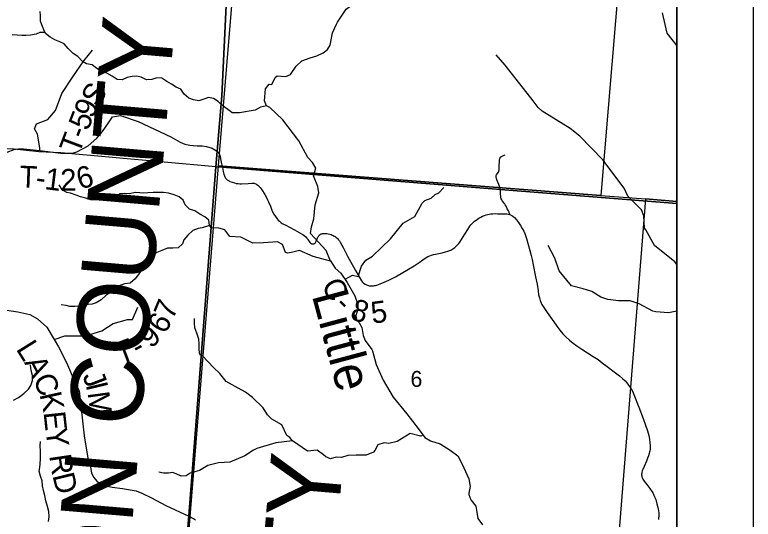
# Model space of a CAD drawing. Extents: x 0 to 42, y 0 to 22.
# Drawn here: x 8.033 to 9, y 16.545 to 17.205 of the extents above; entities that cross this region are included whole.
import ezdxf

# ---------------------------------------------------------------- set-up
doc = ezdxf.new("R2010")
doc.units = 0
for name, color, linetype in [('GM_X_County_Road', 7, 'Continuous'), ('GM_X_County_Road_Text', 7, 'Continuous'), ('GM_X_County_Text', 7, 'Continuous'), ('GM_X_Minor_River', 7, 'Continuous'), ('GM_X_Minor_River_Text', 7, 'Continuous'), ('GM_X_Section', 7, 'Continuous'), ('GM_X_Section_Text', 7, 'Continuous'), ('GM_X_Township', 7, 'Continuous'), ('GM_X_Township_Road', 7, 'Continuous'), ('GM_X_Township_Road_Text', 7, 'Continuous'), ('GM_X_Unincorporated', 7, 'Continuous'), ('SH_Cut_Line', 7, 'Continuous'), ('SH_Data', 7, 'Continuous')]:
    doc.layers.add(name, color=color, linetype=linetype)

msp = doc.modelspace()

# ---------------------------------------------------------------- linework, layer by layer
at = {"layer": 'GM_X_County_Road'}
for points in [[(8.29867, 17.02595), (8.29939, 17.02503), (8.30004, 17.02418), (8.3006, 17.02343), (8.30115, 17.02257), (8.30152, 17.0218), (8.30186, 17.02081), (8.30223, 17.01943), (8.30291, 17.01622), (8.3038, 17.012), (8.30509, 17.00589), (8.30528, 17.00492)], [(8.30528, 17.00492), (8.30629, 16.99983), (8.30713, 16.99616), (8.30787, 16.99385), (8.30833, 16.99284), (8.30888, 16.99182), (8.30938, 16.99108), (8.3103, 16.99), (8.31146, 16.98898), (8.31301, 16.98789), (8.31391, 16.98735), (8.31495, 16.98684), (8.31785, 16.98564), (8.32085, 16.98472), (8.3233, 16.98422), (8.32463, 16.98402), (8.32589, 16.9839), (8.32789, 16.98378), (8.33011, 16.98372), (8.33911, 16.98424), (8.34363, 16.98454), (8.34548, 16.98449), (8.34659, 16.98436), (8.34758, 16.98412), (8.34887, 16.98359), (8.34961, 16.98322), (8.35048, 16.98273), (8.35177, 16.98177), (8.3526, 16.9811), (8.35347, 16.98024), (8.35475, 16.97873), (8.356, 16.97713), (8.35698, 16.97571), (8.36067, 16.96976), (8.36286, 16.96582), (8.36438, 16.96273), (8.36566, 16.95998), (8.368, 16.95444), (8.36948, 16.95049), (8.37087, 16.94712), (8.37252, 16.944), (8.37457, 16.9408), (8.37695, 16.93772), (8.37839, 16.93612), (8.37975, 16.9348), (8.3811, 16.93365), (8.38233, 16.9327), (8.38361, 16.9318), (8.38525, 16.93086), (8.38825, 16.92938), (8.39293, 16.92708), (8.39959, 16.92363), (8.40884, 16.91828), (8.41034, 16.91741), (8.41219, 16.91611), (8.41436, 16.9141), (8.41582, 16.91255), (8.41649, 16.91174), (8.41709, 16.91087), (8.4179, 16.90964), (8.41931, 16.90758), (8.42002, 16.90664), (8.42074, 16.90597), (8.42124, 16.90565), (8.42192, 16.90532), (8.42249, 16.90511), (8.42333, 16.905), (8.42402, 16.90502), (8.42464, 16.90516), (8.42522, 16.90534), (8.42584, 16.9057), (8.42649, 16.9062), (8.42702, 16.90681), (8.42755, 16.90765), (8.42806, 16.90872), (8.42991, 16.91309), (8.43033, 16.91394), (8.43094, 16.91495), (8.43144, 16.91565), (8.43208, 16.91636), (8.43319, 16.91734), (8.43372, 16.91766), (8.43451, 16.91805), (8.43534, 16.91835), (8.43623, 16.91858), (8.43789, 16.91879), (8.43911, 16.91884), (8.44052, 16.91879), (8.44205, 16.91863), (8.44387, 16.91833), (8.44579, 16.91787), (8.4476, 16.91727), (8.44891, 16.91667), (8.45031, 16.91599), (8.45154, 16.9153), (8.45267, 16.9146), (8.45404, 16.91362), (8.45531, 16.91255), (8.45642, 16.91149), (8.45734, 16.91052), (8.45847, 16.9091), (8.4595, 16.9075), (8.46361, 16.89969), (8.46915, 16.88893), (8.4793, 16.87032), (8.48411, 16.86194), (8.48719, 16.85689), (8.48859, 16.85512), (8.49002, 16.85385), (8.49203, 16.85245), (8.49364, 16.85163), (8.49528, 16.85106), (8.4966, 16.85069), (8.49783, 16.8504), (8.49902, 16.85028), (8.50033, 16.85019), (8.50144, 16.85024), (8.50292, 16.8504), (8.50428, 16.85061), (8.50576, 16.85089), (8.50736, 16.8513), (8.51151, 16.8527), (8.51713, 16.85488), (8.52289, 16.85747), (8.53176, 16.86223), (8.5486, 16.87188), (8.55604, 16.87644), (8.56265, 16.88092), (8.56758, 16.88441), (8.57214, 16.88729), (8.57432, 16.88852), (8.57682, 16.88963), (8.57908, 16.89049), (8.58134, 16.89119), (8.58411, 16.89184), (8.5883, 16.89268), (8.59281, 16.89357), (8.59741, 16.8946), (8.60044, 16.89546), (8.60299, 16.89637), (8.60431, 16.89698), (8.60554, 16.89764), (8.60689, 16.8985), (8.60813, 16.89941), (8.60952, 16.90049), (8.61096, 16.90167), (8.6131, 16.90384), (8.61461, 16.90562), (8.61593, 16.90729), (8.61827, 16.91078), (8.62255, 16.91777), (8.62632, 16.92389), (8.62764, 16.92607), (8.6292, 16.92821), (8.63043, 16.92981), (8.63191, 16.93149), (8.63339, 16.93297), (8.63524, 16.93465), (8.63736, 16.93629), (8.63902, 16.9375), (8.64107, 16.93884), (8.64346, 16.9402), (8.64578, 16.94131), (8.64818, 16.94225), (8.65036, 16.94303), (8.65261, 16.94365), (8.65446, 16.94402), (8.6564, 16.94435), (8.65923, 16.94459), (8.66223, 16.9447), (8.66527, 16.94459), (8.67008, 16.94447), (8.67439, 16.94451), (8.67595, 16.94451), (8.67747, 16.94439), (8.67936, 16.9441), (8.68122, 16.94359), (8.68244, 16.94311), (8.68405, 16.94225), (8.68557, 16.94124), (8.68765, 16.93942), (8.69004, 16.93673), (8.69272, 16.93318), (8.69524, 16.92923), (8.69771, 16.92507), (8.69957, 16.92151), (8.70094, 16.91883), (8.70204, 16.91603), (8.70329, 16.91209), (8.70762, 16.89642), (8.70932, 16.88989), (8.71058, 16.8847), (8.71208, 16.87774), (8.71524, 16.86208), (8.7171, 16.85239), (8.71836, 16.84374), (8.71917, 16.83853), (8.72005, 16.83457), (8.72113, 16.83098), (8.7219, 16.82893), (8.72252, 16.82752), (8.7234, 16.82598), (8.72514, 16.82323), (8.7303, 16.81552), (8.73912, 16.80303), (8.7429, 16.79761), (8.74673, 16.7923), (8.75073, 16.78753), (8.75527, 16.78299), (8.75972, 16.77908), (8.76452, 16.77515), (8.76913, 16.77181), (8.77565, 16.76732), (8.79045, 16.75806), (8.7969, 16.75379), (8.80242, 16.7498), (8.80879, 16.74487), (8.81814, 16.73765), (8.82495, 16.73243), (8.82905, 16.72898), (8.83223, 16.72602), (8.8347, 16.72328), (8.83683, 16.7206), (8.83815, 16.71874), (8.84012, 16.71567), (8.84198, 16.71233), (8.84375, 16.70824), (8.85018, 16.69159), (8.85602, 16.67662), (8.85914, 16.66815), (8.86155, 16.66059), (8.8632, 16.65478), (8.86424, 16.6498), (8.86484, 16.64542), (8.86512, 16.64153), (8.86511, 16.63818), (8.86495, 16.6363), (8.86475, 16.63466), (8.86444, 16.63318), (8.86392, 16.63112), (8.86278, 16.62785), (8.8618, 16.62513), (8.86009, 16.621), (8.85704, 16.61396), (8.85535, 16.61014), (8.85468, 16.60829), (8.85421, 16.60675), (8.854, 16.60546), (8.85387, 16.60416), (8.85394, 16.60318), (8.85409, 16.60188), (8.85437, 16.60068), (8.85464, 16.59979), (8.85511, 16.59855), (8.85557, 16.59763), (8.85717, 16.59504), (8.86084, 16.59039), (8.86469, 16.58537), (8.86768, 16.58084), (8.86888, 16.57877), (8.86999, 16.57656), (8.87097, 16.57434), (8.87233, 16.57079), (8.87399, 16.5654), (8.87529, 16.56032), (8.87612, 16.55607), (8.87643, 16.55354), (8.87655, 16.5511), (8.87643, 16.54938), (8.87615, 16.54645), (8.8759, 16.54464)]]:
    msp.add_lwpolyline(points, dxfattribs=at)
at = {"layer": 'GM_X_Minor_River'}
for points in [[(8.36303, 17.0856), (8.36038, 17.09205), (8.36168, 17.10779), (8.36641, 17.11387), (8.36981, 17.11349), (8.37434, 17.1226), (8.3768, 17.12469), (8.38815, 17.12396), (8.3942, 17.12643), (8.40176, 17.13726), (8.40932, 17.14429), (8.4201, 17.14829), (8.42899, 17.15077), (8.43731, 17.15477), (8.44298, 17.15914), (8.44638, 17.16483), (8.44939, 17.18115), (8.45467, 17.19216), (8.45599, 17.195), (8.46732, 17.2119), (8.48018, 17.2216), (8.4917, 17.23546)], [(8.30416, 17.0869), (8.29958, 17.09119), (8.29352, 17.09516), (8.28709, 17.09666), (8.28104, 17.09418), (8.27443, 17.09227), (8.26762, 17.09359), (8.26137, 17.09566), (8.25512, 17.10096), (8.25095, 17.10739), (8.24451, 17.10985), (8.23864, 17.11401), (8.23258, 17.11741), (8.22614, 17.12157), (8.21934, 17.12231), (8.21272, 17.11983), (8.20572, 17.11963), (8.1991, 17.12322), (8.19323, 17.12415), (8.18699, 17.12395), (8.18056, 17.1228), (8.17395, 17.11975), (8.16733, 17.11993), (8.16089, 17.12427), (8.15408, 17.12824), (8.14745, 17.13032), (8.14101, 17.13447), (8.13477, 17.13901), (8.12739, 17.14032), (8.12227, 17.14373), (8.11602, 17.15016), (8.10977, 17.15413), (8.10333, 17.16057), (8.09802, 17.16643), (8.09234, 17.16946), (8.0861, 17.17191), (8.07966, 17.1755), (8.07379, 17.18004), (8.07151, 17.18477), (8.06904, 17.1916), (8.06733, 17.19633), (8.06713, 17.20354), (8.06674, 17.20885)], [(8.88071, 17.20698), (8.88679, 17.18063), (8.9, 17.16388)], [(8.07321, 17.18124), (8.06622, 17.18135), (8.06131, 17.17906), (8.05412, 17.17791), (8.04807, 17.17733), (8.04259, 17.1777), (8.03654, 17.17787), (8.0301, 17.17862)], [(8.9, 16.87828), (8.89753, 16.88182), (8.87083, 16.903), (8.85965, 16.92327), (8.85775, 16.92573), (8.85679, 16.94166), (8.85375, 16.9498), (8.83595, 16.9676), (8.83102, 16.97783), (8.80298, 17.01513), (8.77324, 17.04598), (8.76055, 17.05601), (8.72382, 17.07869), (8.71833, 17.08323), (8.71189, 17.09194), (8.67551, 17.1389), (8.66339, 17.15216)], [(8.42462, 16.99414), (8.42745, 17.00419), (8.42328, 17.01158), (8.41703, 17.01782), (8.40527, 17.03999), (8.38443, 17.06744), (8.36739, 17.08353), (8.36303, 17.0856), (8.35509, 17.08369), (8.34791, 17.0797), (8.32748, 17.07644), (8.31802, 17.07661), (8.31575, 17.07812), (8.30416, 17.0869)], [(8.44688, 16.88269), (8.44119, 16.89633), (8.42036, 16.91866), (8.42167, 16.92758), (8.42487, 16.93801), (8.42675, 16.95603), (8.43165, 16.97177), (8.43012, 16.98011), (8.42462, 16.99414)], [(8.2904, 16.9262), (8.28835, 16.92959), (8.28739, 16.93604), (8.28209, 16.94039), (8.27565, 16.94398), (8.26902, 16.94833), (8.26202, 16.9504), (8.25671, 16.95608), (8.25405, 16.96214), (8.24875, 16.96668), (8.24213, 16.96932), (8.23456, 16.97158), (8.22794, 16.97232), (8.22207, 16.97231), (8.2147, 16.97211), (8.2077, 16.9719), (8.20222, 16.97151), (8.1973, 16.97169), (8.19106, 16.97244), (8.18349, 16.97071), (8.1765, 16.97089), (8.1712, 16.9705), (8.16497, 16.96707), (8.15778, 16.96573), (8.15098, 16.96496), (8.14606, 16.96381), (8.13963, 16.96247), (8.1332, 16.96284), (8.12658, 16.96491), (8.11939, 16.96679), (8.11371, 16.96886), (8.10652, 16.97131), (8.10141, 16.97225), (8.09554, 16.97584), (8.09137, 16.98228)], [(8.4657, 16.85882), (8.47547, 16.86416), (8.48304, 16.86266), (8.48719, 16.87612), (8.49304, 16.88372), (8.50174, 16.88923), (8.52536, 16.91165), (8.54161, 16.93216), (8.5573, 16.9411), (8.56655, 16.95818), (8.57033, 16.9616), (8.57847, 16.96465), (8.58357, 16.96978), (8.58867, 16.97188), (8.5951, 16.97891)], [(8.28852, 16.92931), (8.27871, 16.92616), (8.2736, 16.92539), (8.26661, 16.92272), (8.26019, 16.91645), (8.25491, 16.91018), (8.25284, 16.90525), (8.24755, 16.89993), (8.24055, 16.89953), (8.23356, 16.89971), (8.226, 16.89666), (8.21957, 16.8938), (8.21277, 16.88923), (8.20711, 16.88316), (8.20239, 16.87784), (8.19919, 16.87081), (8.19579, 16.86607), (8.19108, 16.85942), (8.18447, 16.85371), (8.17709, 16.85275), (8.1701, 16.85027), (8.16387, 16.84552), (8.15877, 16.84134), (8.1531, 16.83791), (8.1465, 16.83183), (8.14007, 16.82821), (8.13459, 16.8265), (8.12967, 16.82592), (8.12287, 16.82439), (8.11776, 16.82381), (8.11228, 16.82304), (8.10547, 16.8234), (8.10055, 16.82472), (8.09412, 16.82546)], [(8.44688, 16.88269), (8.42398, 16.88871), (8.406, 16.89626), (8.3973, 16.89416), (8.39068, 16.89282), (8.38803, 16.89376), (8.38405, 16.90418), (8.37742, 16.90777), (8.35888, 16.9066), (8.34526, 16.90582), (8.32955, 16.91394), (8.31498, 16.91486), (8.30854, 16.92357), (8.30059, 16.92545), (8.2904, 16.9262)], [(8.9, 16.81707), (8.88909, 16.81506), (8.87244, 16.81636), (8.86847, 16.81692), (8.85067, 16.82693), (8.83913, 16.83051), (8.82381, 16.83049), (8.8098, 16.83217), (8.80072, 16.83556), (8.7886, 16.84275), (8.77763, 16.84652), (8.76211, 16.85047), (8.74601, 16.86978), (8.74012, 16.88626), (8.7314, 16.90312)], [(8.44679, 16.88291), (8.45298, 16.87343), (8.46018, 16.86699), (8.46852, 16.85466), (8.47857, 16.83701), (8.48255, 16.82581), (8.48237, 16.81973), (8.47973, 16.81099), (8.48049, 16.80682), (8.48371, 16.80264), (8.48769, 16.79562), (8.48959, 16.78518), (8.49225, 16.77892), (8.50078, 16.76697), (8.50154, 16.76545), (8.50647, 16.74761), (8.51577, 16.72711), (8.52885, 16.70472), (8.54647, 16.68291), (8.56126, 16.66375), (8.56998, 16.65218), (8.57755, 16.64745), (8.59005, 16.64348), (8.6035, 16.63553), (8.61354, 16.62795), (8.61923, 16.61732), (8.62795, 16.59778), (8.62948, 16.58771), (8.62778, 16.57916), (8.62778, 16.57726), (8.63044, 16.57043), (8.63688, 16.56209), (8.63783, 16.55696), (8.63973, 16.54614), (8.6458, 16.5376)], [(8.27617, 16.76003), (8.27504, 16.76212), (8.27465, 16.76781), (8.27483, 16.77426), (8.27444, 16.78033), (8.27178, 16.78829), (8.26931, 16.7953), (8.26892, 16.80155), (8.26872, 16.80762)], [(8.3971, 16.64748), (8.3936, 16.65184), (8.38943, 16.65448), (8.3828, 16.66831), (8.36973, 16.67606), (8.36443, 16.68155), (8.35837, 16.69064), (8.34473, 16.70426), (8.33526, 16.71126), (8.32182, 16.71844), (8.31009, 16.72525), (8.30175, 16.73585), (8.2936, 16.74342), (8.27903, 16.75862), (8.27617, 16.76003)], [(8.03175, 16.70056), (8.03855, 16.70418), (8.04535, 16.70969), (8.05158, 16.71502), (8.0546, 16.71976), (8.05667, 16.72659), (8.05666, 16.73304), (8.05494, 16.73967), (8.05398, 16.74669)], [(8.56787, 16.65511), (8.56443, 16.65386), (8.55081, 16.65725), (8.53379, 16.64679), (8.5232, 16.64431), (8.51715, 16.64505), (8.50864, 16.64219), (8.50486, 16.63517), (8.50278, 16.6327), (8.49352, 16.6287), (8.48046, 16.62906), (8.4693, 16.62847), (8.46117, 16.62561), (8.45417, 16.62616), (8.4466, 16.62387), (8.44055, 16.62671), (8.43771, 16.62936), (8.42919, 16.63522), (8.41651, 16.63425), (8.39682, 16.64767), (8.37526, 16.64479), (8.35048, 16.63773), (8.34613, 16.63525), (8.3346, 16.62784), (8.31493, 16.61965), (8.29999, 16.61886), (8.28637, 16.61542), (8.27521, 16.60895), (8.26294, 16.60554)], [(8.07762, 16.54214), (8.07837, 16.54839), (8.07817, 16.55503), (8.07626, 16.56166), (8.07417, 16.56924), (8.07302, 16.57626), (8.07112, 16.58251), (8.06978, 16.58896), (8.0692, 16.5954), (8.0673, 16.60146), (8.06559, 16.60791), (8.06615, 16.61265), (8.06689, 16.61758), (8.06726, 16.62403), (8.06724, 16.63427), (8.06666, 16.64091), (8.06722, 16.64678)], [(8.26294, 16.60554), (8.25775, 16.60186), (8.25113, 16.60127), (8.24489, 16.6043), (8.23978, 16.60618), (8.23448, 16.60522), (8.22824, 16.60521), (8.222, 16.60671)]]:
    msp.add_lwpolyline(points, dxfattribs=at)
at = {"layer": 'GM_X_Section'}
for points in [[(8.3427, 17.52106), (8.84322, 17.47731), (8.8004, 16.96848), (8.30008, 17.00734)], [(8.30008, 17.00734), (8.8004, 16.96848), (8.85894, 16.96397), (8.81895, 16.45969), (8.25964, 16.50525)]]:
    msp.add_lwpolyline(points, close=True, dxfattribs=at)
at = {"layer": 'GM_X_Township'}
msp.add_lwpolyline([(8.42127, 18.51405), (8.38769, 18.10646), (8.32232, 17.47301), (8.30468, 17.09885), (8.29856, 17.02621), (8.2967, 17.00562), (8.09356, 17.02392), (8.06488, 17.0255), (8.03278, 17.02883), (7.97896, 17.0312), (7.36254, 17.08083), (7.35717, 17.08127), (7.35122, 17.08175), (7.35051, 17.0818), (7.34212, 17.08248), (7.2769, 17.08773), (7.22466, 17.09014), (6.78886, 17.12464), (6.70312, 17.1317), (6.64854, 17.1358), (6.05163, 17.18401)], dxfattribs=at)
at = {"layer": 'GM_X_Township_Road'}
for points in [[(8.9, 16.95771), (8.9, 20.00639), (8.75955, 20.01746), (8.65628, 20.02413), (8.5294, 20.03351), (8.48531, 19.43126), (8.46517, 19.12289), (8.46366, 19.1008), (8.46152, 19.07253), (8.46207, 19.06399), (8.4621, 19.05934), (8.4614, 19.04662), (8.46117, 19.04011), (8.46085, 19.02695), (8.42127, 18.51405), (8.38769, 18.10646), (8.32232, 17.47301), (8.30468, 17.09885), (8.29856, 17.02621), (8.2967, 17.00562), (8.30518, 17.00518), (8.669, 16.9761)], [(8.05023, 14.1), (8.9, 14.1), (8.9, 16.95771), (8.669, 16.9761), (8.30518, 17.00518), (8.2967, 17.00562), (8.26133, 16.54947), (8.24231, 16.32059), (8.17227, 15.49063), (8.16983, 15.46634), (8.16945, 15.45935), (8.16837, 15.44612), (8.1628, 15.37905), (8.15761, 15.31908), (8.1512, 15.24132), (8.08338, 14.51358), (8.06868, 14.30702)]]:
    msp.add_lwpolyline(points, close=True, dxfattribs=at)
for points in [[(8.17227, 15.49063), (8.24231, 16.32059), (8.26133, 16.54947), (8.2967, 17.00562), (8.09356, 17.02392), (8.06488, 17.0255), (8.03278, 17.02883), (7.97896, 17.0312), (7.36254, 17.08083), (7.35717, 17.08127), (7.35122, 17.08175), (7.35051, 17.0818), (7.34212, 17.08248), (7.2769, 17.08773), (7.22466, 17.09014), (6.78886, 17.12464), (6.70312, 17.1317), (6.64854, 17.1358), (6.05163, 17.18401)], [(8.06632, 17.02731), (8.06623, 17.03086), (8.06318, 17.04851), (8.05946, 17.05532), (8.06195, 17.06196), (8.07655, 17.0678), (8.08682, 17.07953), (8.09523, 17.10152), (8.10951, 17.12331), (8.12397, 17.14452), (8.13542, 17.15852)], [(8.10496, 17.02371), (8.10903, 17.02373), (8.11484, 17.02534), (8.12965, 17.03347), (8.14067, 17.04331), (8.14827, 17.05221), (8.15626, 17.06319), (8.16121, 17.07114), (8.17201, 17.07282), (8.1949, 17.06497), (8.23793, 17.04498), (8.25002, 17.03815), (8.25623, 17.03526), (8.26275, 17.03411), (8.27204, 17.0333), (8.27866, 17.0333), (8.28424, 17.03257), (8.29189, 17.0302), (8.29867, 17.02595)], [(7.99785, 17.01097), (8.01445, 17.02171), (8.03288, 17.02857), (8.03831, 17.02931), (8.04473, 17.02952), (8.06632, 17.02731), (8.09367, 17.02366), (8.10496, 17.02371)], [(8.6691, 16.97584), (8.66877, 16.97732), (8.66804, 16.97994), (8.66688, 16.9829), (8.66461, 16.98865), (8.66378, 16.99111), (8.66355, 16.99201), (8.66341, 16.99285), (8.66343, 16.99345), (8.66355, 16.99418), (8.66372, 16.99465), (8.6641, 16.9954), (8.66488, 16.99661), (8.66641, 16.9989), (8.66688, 16.99984), (8.66721, 17.00065), (8.66738, 17.00143), (8.66744, 17.00221), (8.66749, 17.00397), (8.66767, 17.00725), (8.66787, 17.01275), (8.66795, 17.01492), (8.66804, 17.01557), (8.66814, 17.01614), (8.66833, 17.01676), (8.66858, 17.0173), (8.66891, 17.01784), (8.66927, 17.01832), (8.66975, 17.01879), (8.67019, 17.01915), (8.67077, 17.01946), (8.67145, 17.01979), (8.67402, 17.021), (8.67544, 17.02168)], [(8.68122, 16.94359), (8.68097, 16.94463), (8.68076, 16.94553), (8.68038, 16.94654), (8.67965, 16.94813), (8.67802, 16.9509), (8.67741, 16.95218), (8.67655, 16.95426), (8.67544, 16.95631), (8.67433, 16.95779), (8.67176, 16.96091), (8.67079, 16.96248), (8.67019, 16.96402), (8.66969, 16.96627), (8.66948, 16.96813), (8.66939, 16.9697), (8.66934, 16.97124), (8.66939, 16.97334), (8.6692, 16.97543), (8.6691, 16.97584)], [(8.01395, 16.81956), (8.03761, 16.81645), (8.05332, 16.81261), (8.06315, 16.80708), (8.07561, 16.79622), (8.08501, 16.7802), (8.09067, 16.77056), (8.1012, 16.75003), (8.11266, 16.72342), (8.11755, 16.71316), (8.12416, 16.65431), (8.12918, 16.62507), (8.13281, 16.61374), (8.13395, 16.60526), (8.13705, 16.59958), (8.14087, 16.59472), (8.14666, 16.59079), (8.15224, 16.58893), (8.16082, 16.58717), (8.17426, 16.58521), (8.19235, 16.58232), (8.19958, 16.57932), (8.2123, 16.57301), (8.23131, 16.56319), (8.26144, 16.54921)], [(8.08501, 16.7802), (8.09895, 16.78476), (8.12587, 16.78476), (8.14741, 16.79149), (8.16221, 16.8009), (8.18105, 16.80629), (8.18778, 16.80629), (8.19451, 16.82244)], [(8.27017, 16.5437), (8.26736, 16.54561), (8.26343, 16.54801), (8.26144, 16.54921)]]:
    msp.add_lwpolyline(points, dxfattribs=at)
at = {"layer": 'GM_X_Unincorporated'}
for points in [[(8.9, 16.96072), (8.9, 17.47238), (8.84322, 17.47731), (8.8004, 16.96848), (8.85894, 16.96397)], [(8.9, 16.45296), (8.9, 16.96072), (8.85894, 16.96397), (8.81895, 16.45969)]]:
    msp.add_lwpolyline(points, close=True, dxfattribs=at)
at = {"layer": 'SH_Cut_Line'}
for points in [[(8.17227, 15.49063), (8.24231, 16.32059), (8.26133, 16.54947), (8.2967, 17.00562), (8.29856, 17.02621), (8.30468, 17.09885), (8.32232, 17.47301), (8.38769, 18.10646), (8.42127, 18.51405), (8.46085, 19.02695), (8.46117, 19.04011), (8.4614, 19.04662), (8.4621, 19.05934), (8.46207, 19.06399), (8.46152, 19.07253), (8.46366, 19.1008), (8.46517, 19.12289), (8.48531, 19.43126), (8.5294, 20.03351), (8.55155, 20.24789), (8.57059, 20.47391), (8.6039, 20.89865), (8.604, 20.9), (2.1, 20.9)], [(8.9, 14.1), (8.9, 20.00639), (8.75955, 20.01746), (8.65628, 20.02413), (8.5294, 20.03351), (8.48531, 19.43126), (8.46517, 19.12289), (8.46366, 19.1008), (8.46152, 19.07253), (8.46207, 19.06399), (8.4621, 19.05934), (8.4614, 19.04662), (8.46117, 19.04011), (8.46085, 19.02695), (8.42127, 18.51405), (8.38769, 18.10646), (8.32232, 17.47301), (8.30468, 17.09885), (8.29856, 17.02621), (8.2967, 17.00562), (8.26133, 16.54947), (8.24231, 16.32059), (8.17227, 15.49063)]]:
    msp.add_lwpolyline(points, dxfattribs=at)
at = {"layer": 'SH_Data'}
for p, q in [((9, 21), (9, 14)), ((8.9, 20.9), (8.9, 14.1))]:
    msp.add_line(p, q, dxfattribs=at)

# ---------------------------------------------------------------- texts
at = {"layer": 'GM_X_County_Road_Text'}
for s, rotation, p in [('C', 298.08902, (8.43422, 16.85123)), ('-', 314.10306, (8.4503, 16.82366)), ('8', 341.75598, (8.47098, 16.80741)), ('5', 7.68675, (8.50147, 16.80065))]:
    msp.add_text(s, height=0.02841, rotation=rotation, dxfattribs=at).set_placement(p)
at = {"layer": 'GM_X_County_Text'}
for s, rotation, p in [('JACKSON COUNTY', 85.11732, (8.14398, 16.03335)), ('GALLIA COUNTY', 85.10167, (8.3773, 15.61717))]:
    msp.add_text(s, height=0.094697, rotation=rotation, dxfattribs=at).set_placement(p)
at = {"layer": 'GM_X_Minor_River_Text'}
msp.add_text('Little', height=0.047341, rotation=285.00107, dxfattribs=at).set_placement((8.42207, 16.83804))
at = {"layer": 'GM_X_Section_Text'}
msp.add_text('6', height=0.02093, rotation=0.00001, dxfattribs=at).set_placement((8.5514, 16.7181))
at = {"layer": 'GM_X_Township_Road_Text'}
for s, rotation, p in [('S', 57.09006, (8.14209, 17.08283)), ('9', 66.11465, (8.13556, 17.06787)), ('5', 68.6083, (8.1293, 17.05188)), ('T', 69.32557, (8.11769, 17.02118)), ('-', 69.19452, (8.12519, 17.04104)), ('T', 357.72806, (8.03925, 16.97906)), ('1', 352.97157, (8.07159, 16.97674)), ('2', 1.16463, (8.09338, 16.97438)), ('6', 15.80323, (8.11868, 16.9759)), ('-', 352.5797, (8.05981, 16.97828)), ('7', 67.46835, (8.24048, 16.80491)), ('6', 59.61716, (8.22974, 16.78601)), ('9', 43.91478, (8.2119, 16.76723)), ('L', 301.95678, (8.03446, 16.76766)), ('T', 20.36121, (8.17099, 16.74759)), ('-', 28.2124, (8.19477, 16.75673)), ('A', 297.20529, (8.0454, 16.75018)), ('C', 294.20978, (8.05665, 16.72829)), ('J', 290.78548, (8.12169, 16.73258)), ('I', 283.30355, (8.12613, 16.72106)), ('K', 282.58453, (8.06574, 16.70846)), ('M', 277.68483, (8.12868, 16.71043)), ('E', 276.14427, (8.07105, 16.68489)), ('Y', 277.70897, (8.07343, 16.66292)), ('R', 278.453, (8.0786, 16.62827)), ('D', 283.68932, (8.08258, 16.6024))]:
    msp.add_text(s, height=0.02841, rotation=rotation, dxfattribs=at).set_placement(p)

doc.saveas('drawing.dxf')
